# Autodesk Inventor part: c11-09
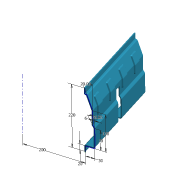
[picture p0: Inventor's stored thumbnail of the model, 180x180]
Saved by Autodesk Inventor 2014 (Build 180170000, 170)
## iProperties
Created: 2011-01
Part Number: c11-09
Material: Aluminum 6061
Document SubType Name: Sheet Metal
Designer: Thom Tremblay
Density: 2.71 g/cm^3
Sheet Metal Rule: Aluminum - 3.4mm
Appearance: Turquoise
Author: Thom Tremblay
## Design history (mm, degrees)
sketch "Sketch1"
  geometry: L1 (0, 0)-(20, 0); L2 (20, 0)-(20, 30); L3 (20, 30)-(90, 30); L4 (100.392, 24)-(150, 24); L5 (150, 24)-(200, 5.801); L6 (200, 5.801)-(200, 0); L7 (200, 0)-(220, 0); L8 (90, 30)-(100.392, 24); L9 (201.956, -200)-(-5.105, -200); 1 further point
  constraints: 18 end point, 4 parallel, 3 collinear, 1 coincident, 1 horizontal, 1 perpendicular
  dimensions: "d5" = 20 distance of L1.start L1.end; "d6" = 30 distance of L1.end L2.end; "d7" = 70 distance of L2.end L3.end; "d9" = 220 distance of L7.end point (0, 0); "d11" = 20 deg angle of L5 L4; "d13" = 6 vertical distance of L3.end L4.start; "d14" = 130 distance from line of L4.end L2; "d15" = 30 deg angle of L8 L3; "d46" = 200 distance between parallel lines of L1 L9
node "Contour Flange1"
sketch "Sketch3" dims "d35" = 10
  geometry: L1 (100.928, 0)-(100.928, -300) reference; L2 (82.928, 0)-(100.928, 0) reference; 4 further points
  constraints: 1 vertical, 3 other
  dimensions: "d29" = 40 distance from line of L2 point (-49.072, -40); "d32" = 73 distance of point (-49.072, -40) point (-49.072, -113); "d47" = 150 distance from line of L1 point (-49.072, -40)
node "Unfold1"
feature "iFeature4:1"
node "Refold1"
sketch "Sketch4"
  geometry: L1 (65.4, -140)-(-108.648, -140); L2 (-108.648, -140)-(-108.648, -160); L3 (-108.648, -160)-(65.4, -160); L4 (65.4, -160)-(65.4, -140); L5 (25.4, 0)-(25.4, -300) reference; L6 (93.374, -103.348)-(93.374, -122.652) reference; L7 (-98.951, -97.771)-(-124.951, -97.771) reference; L8 (-124.951, -300)-(-124.951, -274.229) reference; L9 (-124.951, -55.229)-(-98.951, -55.229) reference; L10 (93.374, -30.348)-(93.374, -49.652) reference; L11 (-98.951, -24.771)-(-124.951, -24.771) reference; L12 (-124.951, -300)-(-124.951, -274.229) reference; L13 (-124.951, 0)-(-76.831, 0) reference; L14 (-76.831, -300)-(-124.951, -300) reference; L15 (-124.951, -300)-(-124.951, -274.229) reference; L16 (-63.153, -300)-(-63.153, 0) reference; L17 (-64.984, -300)-(-64.984, 0) reference; L18 (-75.001, -300)-(-75.001, 0) reference; L19 (-76.831, -300)-(-76.831, 0) reference; L20 (-75.916, -300)-(-75.916, 0) reference; L21 (-98.951, -243.771)-(-124.951, -243.771) reference; L22 (-124.951, -300)-(-124.951, -274.229) reference; L23 (-63.153, -300)-(-64.984, -300) reference; L24 (-64.984, 0)-(-63.153, 0) reference; L25 (0, -300)-(-63.153, -300) reference; L26 (0, -300)-(0, 0) reference; L27 (-63.153, 0)-(0, 0) reference; L28 (-124.951, -201.229)-(-98.951, -201.229) reference; L29 (-75.001, 0)-(-64.984, 0) reference; L30 (-64.984, -300)-(-75.001, -300) reference; L31 (-76.831, 0)-(-75.001, 0) reference; L32 (-75.001, -300)-(-76.831, -300) reference; L33 (-124.951, -274.229)-(-98.951, -274.229) reference; L34 (93.374, -249.348)-(93.374, -268.652) reference; L35 (93.374, -176.348)-(93.374, -195.652) reference; L36 (-98.951, -170.771)-(-124.951, -170.771) reference; L37 (-124.951, -300)-(-124.951, -274.229) reference; L38 (-124.951, -128.229)-(-98.951, -128.229) reference; L39 (-64.068, 0)-(-64.068, -300) reference; L40 (-123.648, -170.771)-(-123.648, -128.229) reference; A1 r 5.577 centre (98.951, -103.348) between (98.951, -97.771) and (93.374, -103.348) reference; A2 r 5.577 centre (98.951, -49.652) between (93.374, -49.652) and (98.951, -55.229) reference; A3 r 5.577 centre (98.951, -30.348) between (98.951, -24.771) and (93.374, -30.348) reference; A4 r 5.577 centre (98.951, -195.652) between (93.374, -195.652) and (98.951, -201.229) reference; A5 r 5.577 centre (98.951, -268.652) between (93.374, -268.652) and (98.951, -274.229) reference; A6 r 5.577 centre (98.951, -249.348) between (98.951, -243.771) and (93.374, -249.348) reference; A7 r 5.577 centre (98.951, -176.348) between (98.951, -170.771) and (93.374, -176.348) reference; A8 r 5.577 centre (98.951, -122.652) between (93.374, -122.652) and (98.951, -128.229) reference; 2 further points
  constraints: 8 end point, 2 midpoint, 2 parallel, 1 horizontal, 1 horizontal alignment, 1 perpendicular
  dimensions: "d41" = 20 distance of L3.end L1.start; "d42" = 40 distance between parallel lines of L5 L4; "d48" = 15 distance between parallel lines of L2 L40
cut "Cut1" sketch "Sketch4" dims "d44" = 3.4 (= Thickness), "d45" = 0
body "Solid2"
face "Plate2" dims "d16" = 3.4 (= BendReliefWidth), "d17" = 1.7 (= BendReliefDepth), "d18" = 6.8 (= MinimumRemnant), "d19" = 2 (= BendRadius), "d20" = 300, "d21" = 2 (= BendRadius), "d22" = 3.4, "d23" = 13.6 (= CornerReliefSize), "d24" = 3.4 (= GapSize), "d25" = 2 (= JacobiRadiusSize), "SeamGap" = 0.01, "Thickness" = 3.4 (derived)
bend "Bend1" dims "d16" = 3.4 (= BendReliefWidth), "d17" = 1.7 (= BendReliefDepth), "d18" = 6.8 (= MinimumRemnant), "d19" = 2 (= BendRadius), "d21" = 2 (= BendRadius), "d22" = 3.4, "SeamGap" = 0.01, "Thickness" = 3.4 (derived)
feature "Corner1" dims "d22" = 3.4, "d23" = 13.6 (= CornerReliefSize), "d24" = 3.4 (= GapSize), "d25" = 2 (= JacobiRadiusSize)
other parameters: "BendRadius" = 2 (derived), "BendReliefWidth" = 3.4 (= Thickness), "BendReliefDepth" = 1.7 (= 0.5 x Thickness), "CornerReliefSize" = 13.6 (= 4 x Thickness), "MinimumRemnant" = 6.8 (= 2 x Thickness), "TransitionRadius" = 2 (= BendRadius), "JacobiRadiusSize" = 2 (= BendRadius), "GapSize" = 3.4 (= Thickness), "d4" = 2 (= BendRadius), "d40" = 0
